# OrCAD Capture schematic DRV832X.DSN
size B; title: DRV832x DRIVER
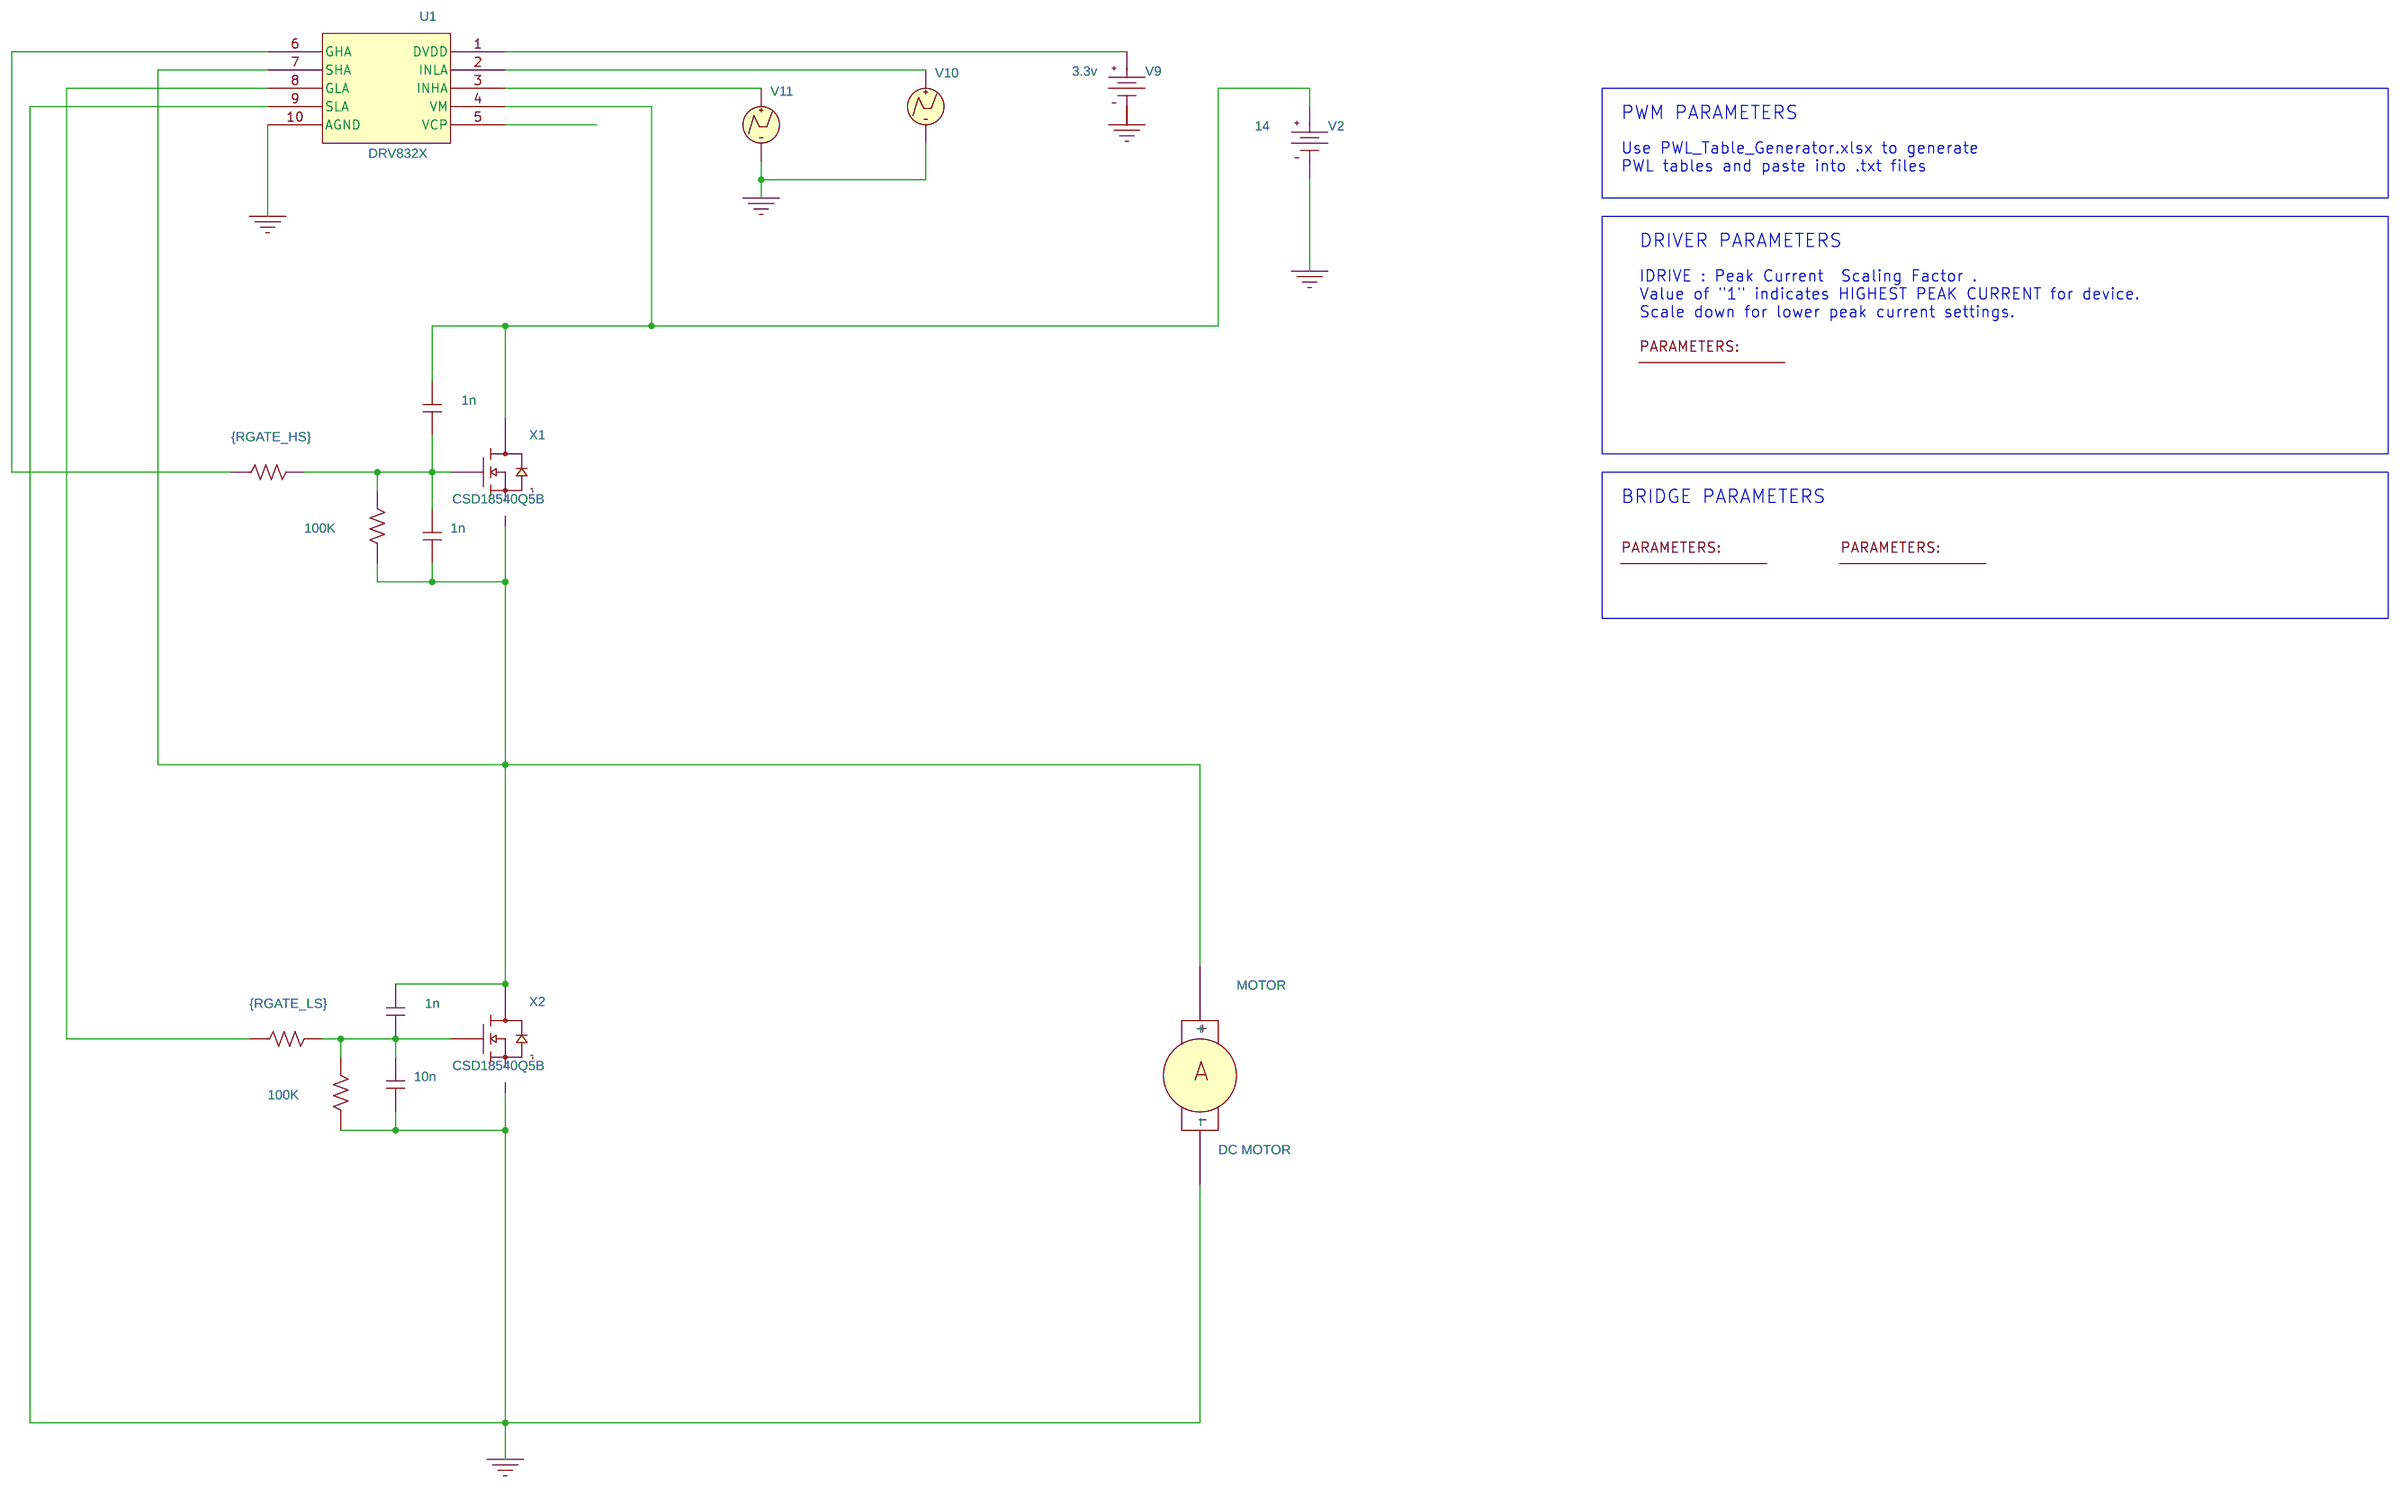
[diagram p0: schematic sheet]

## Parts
10  PARAM
11  PARAM
12  PARAM
C_BSTA6  1n  [RAD/CK05]
C_BSTA8  1n  [RAD/CK05]
C_BSTA23  10n  [RAD/CK05]
C_BSTA24  1n  [RAD/CK05]
MOTOR  DC MOTOR
RGATE1  {RGATE_LS}  [AX/RC05]
RGATE2  {RGATE_HS}  [AX/RC05]
RVgs1  100K  [AX/RC05]
RVgs6  100K  [AX/RC05]
U1  DRV832X
V2  VDC
V9  VDC
V10  VPWL_GENERIC
V11  VPWL_GENERIC
X1  CSD18540Q5B
X2  CSD18540Q5B

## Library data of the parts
10 = PARAM: IDRIVE_HSPD: 1; IDRIVE_HSPU: 1; IDRIVE_LSPD: 1; IDRIVE_LSPU: 0.001
11 = PARAM: RGATE_HS: 1
12 = PARAM: RGATE_LS: 1
C_BSTA6 C_BSTA8 C_BSTA23 C_BSTA24 = C: VOLTAGE: CMAX
MOTOR = MOTOR_SERVO: PSpiceTemplate: X^@REFDES %+ %- @MODEL
RGATE1 RGATE2 RVgs1 RVgs6 = R
U1 = DRV832X
V2 = VDC: DC: 14
V9 = VDC: DC: 3.3v
V10 = VPWL_GENERIC: AppProp: No_reps$POINTS_TYPE_PWL$0$0; FIRST_NPAIRS: 0 0 6u 0 6.1u 3.3 10u 3.3 10.1u 0 16u 0 16.1u 3.3 20u 3.3 20.1u 0; PSpiceTemplate: V^@REFDES %+ %- ?DC|DC @DC| ?AC|AC @AC| PWL ?TSF|TIME_SCALE_FACTOR=@TSF| ?VSF|VALUE_SCALE_FACTOR=@VSF| ?REPEAT_VALUE| \n+ REPEAT FOR @REPEAT_VALUE| \n+ @FIRST_NPAIRS ?SECOND_NPAIRS|\n+ @SECOND_NPAIRS ?THIRD_NPAIRS/\n+ @THIRD_NPAIRS/| ?REPEAT_VALUE| \n+ ENDREPEAT|
V11 = VPWL_GENERIC: AppProp: No_reps$POINTS_TYPE_PWL$0$0; FIRST_NPAIRS: 0 0 1u 0 1.1u 3.3 5u 3.3 5.1u 0 11u 0 11.1u 3.3 15u 3.3 15.1u 0; PSpiceTemplate: V^@REFDES %+ %- ?DC|DC @DC| ?AC|AC @AC| PWL ?TSF|TIME_SCALE_FACTOR=@TSF| ?VSF|VALUE_SCALE_FACTOR=@VSF| ?REPEAT_VALUE| \n+ REPEAT FOR @REPEAT_VALUE| \n+ @FIRST_NPAIRS ?SECOND_NPAIRS|\n+ @SECOND_NPAIRS ?THIRD_NPAIRS/\n+ @THIRD_NPAIRS/| ?REPEAT_VALUE| \n+ ENDREPEAT|
X1 = CSD18540Q5B
X2 = CSD18540Q5B_1

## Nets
0: C_BSTA23.1 MOTOR.2(-) RVgs1.1 U1.9(SLA) U1.10(AGND) V2.1(-) V9.1(-) V10.2(-) V11.2(-) X2.source
N15096192: C_BSTA8.1 C_BSTA24.1 MOTOR.1(+) RVgs6.1 U1.7(SHA) X1.source X2.drain
N15096326: RGATE1.1 U1.8(GLA)
N15100202: RGATE2.1 U1.6(GHA)
N15100877: U1.2(INLA) V10.1(+)
N15135072: C_BSTA6.2 C_BSTA8.2 RGATE2.2 RVgs6.2 X1.gate
N15135559: C_BSTA23.2 C_BSTA24.2 RGATE1.2 RVgs1.2 X2.gate
N15140326: U1.3(INHA) V11.1(+)
N15142260: C_BSTA6.1 U1.4(VM) V2.0(+) X1.drain
N15184068: U1.1(DVDD) V9.0(+)

Not connected (* = marked no-connect by the designer): U1 5(VCP)

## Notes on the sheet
- PWM PARAMETERS
- Use PWL_Table_Generator.xlsx to generate
  PWL tables and paste into .txt files
- DRIVER PARAMETERS
- IDRIVE : Peak Current  Scaling Factor .
  Value of "1" indicates HIGHEST PEAK CURRENT for device.
  Scale down for lower peak current settings.
- BRIDGE PARAMETERS
